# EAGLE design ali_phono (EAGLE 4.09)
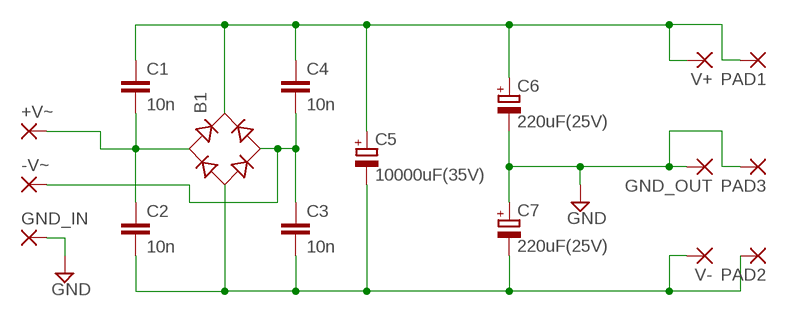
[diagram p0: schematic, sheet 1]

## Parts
+V~  3,17/1,1  [3,17/1,1]
-V~  3,17/1,1  [3,17/1,1]
B1  RB1A  [RB1A]
C1  10n  C-EU050-025X075  [C050-025X075]
C2  10n  C-EU050-025X075  [C050-025X075]
C3  10n  C-EU050-025X075  [C050-025X075]
C4  10n  C-EU050-025X075  [C050-025X075]
C5  10000uF(35V)  CPOL-EUE10-35  [EB35D]
C6  220uF(25V)  CPOL-EUE5-10.5  [E5-10,5]
C7  220uF(25V)  CPOL-EUE5-10.5  [E5-10,5]
GND_IN  3,17/1,1  [3,17/1,1]
GND_OUT  3,17/1,1  [3,17/1,1]
PAD1  3,17/1,1  [3,17/1,1]
PAD2  3,17/1,1  [3,17/1,1]
PAD3  3,17/1,1  [3,17/1,1]
V+  3,17/1,1  [3,17/1,1]
V-  3,17/1,1  [3,17/1,1]

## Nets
GND: C6.- C7.+ GND_IN.1(P) GND_OUT.1(P) PAD3.1(P)
N$1: +V~.1(P) B1.AC1 C1.2 C2.1
N$2: B1.+ C1.1 C4.1 C5.+ C6.+ PAD1.1(P) V+.1(P)
N$5: B1.- C2.2 C3.2 C5.- C7.- PAD2.1(P) V-.1(P)
N$12: -V~.1(P) B1.AC2 C3.1 C4.2

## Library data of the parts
+V~ -V~ GND_IN GND_OUT PAD1-PAD3 V+ V- = wirepad:3,17/1,1: THROUGH-HOLE PAD
B1 = rectifier:RB1A: RECTIFIER 1 A
C1-C4 = rcl:C-EU: CAPACITOR, European symbol
C5-C7 = rcl:CPOL-EU: POLARIZED CAPACITOR, European symbol

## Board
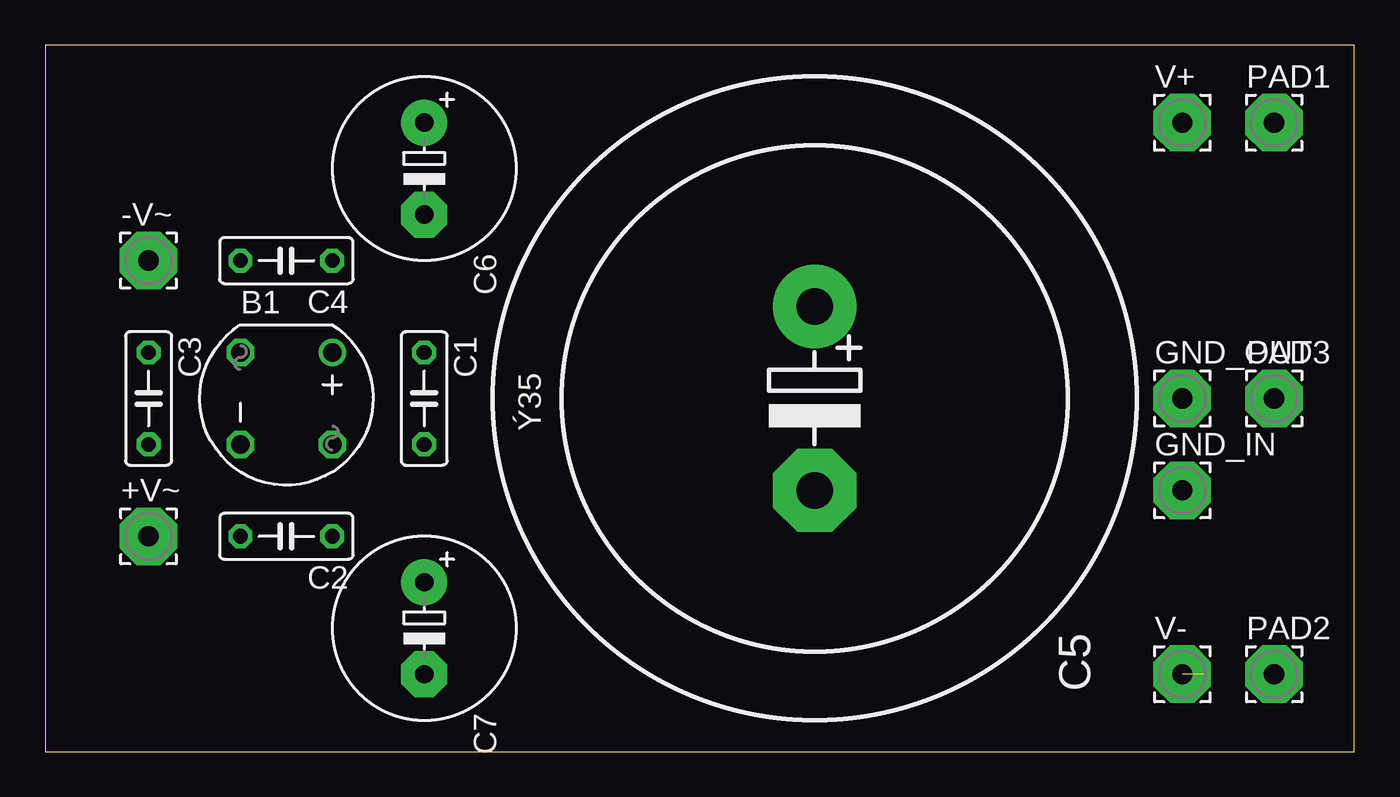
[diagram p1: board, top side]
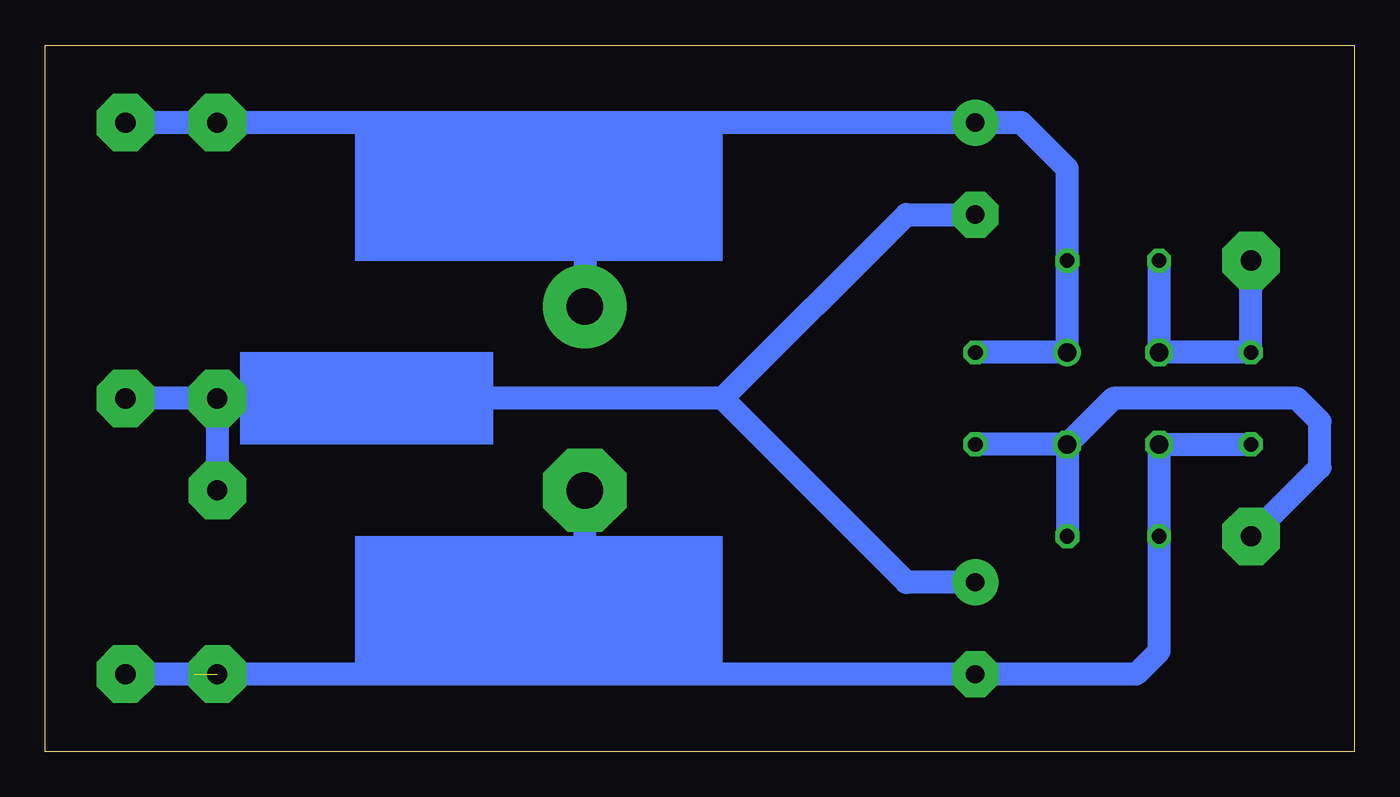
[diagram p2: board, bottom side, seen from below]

Size 72.37 x 39.04 mm. Coordinates in mm from the lower left corner, seen from the top.
Outline: 0,0 72.37,0 72.37,39.04 0,39.04 0,0
Copper layers used: Bottom

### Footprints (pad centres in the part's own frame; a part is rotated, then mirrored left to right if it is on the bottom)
3,17/1,1 = drill 1.118 pad 3.175 octagon: 1 0,0
RB1A = drill 1.016 round: + -2.54,2.54 | drill 1.016 octagon: - 2.54,-2.54; AC1 2.54,2.54; AC2 -2.54,-2.54
C050-025X075 = drill 0.813 octagon: 1 -2.54,0; 2 2.54,0
EB35D = drill 2.007 pad 4.597 round: + -5.08,0 | drill 2.007 pad 4.597 octagon: - 5.08,0
E5-10,5 = drill 1.016 pad 2.54 round: + -2.54,0 | drill 1.016 pad 2.54 octagon: - 2.54,0

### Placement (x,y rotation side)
+V~  5.71,11.9 0 top
-V~  5.71,27.14 0 top
B1  13.33,19.52 270 top
C1  20.95,19.52 270 top
C2  13.33,11.9 180 top
C3  5.71,19.52 270 top
C4  13.33,27.14 180 top
C5  42.54,19.52 270 top
C6  20.95,32.22 270 top
C7  20.95,6.82 270 top
GND_IN  62.86,14.44 0 top
GND_OUT  62.86,19.52 0 top
PAD1  67.94,34.76 0 top
PAD2  67.94,4.28 0 top
PAD3  67.94,19.52 0 top
V+  62.86,34.76 0 top
V-  62.86,4.28 0 top

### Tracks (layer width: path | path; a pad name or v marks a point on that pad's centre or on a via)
GND
  Bottom 1.27: 34.92,19.52 GND_OUT.1 | 34.92,19.52 24.76,29.68 C6.- | C7.+ 24.76,9.36 34.92,19.52 | GND_OUT.1 GND_IN.1 | GND_OUT.1 PAD3.1
N$1
  Bottom 1.27: B1.AC1 C2.1 B1.AC1 | B1.AC1 C1.2 | B1.AC1 13.33,19.52 3.17,19.52 1.9,18.25 1.9,15.71 +V~.1
N$2
  Bottom 1.27: 42.54,34.76 C6.+ 18.41,34.76 15.87,32.22 C4.1 B1.+ C1.1 | 42.54,34.76 V+.1 PAD1.1 | 42.54,34.76 C5.+
N$5  (1 unrouted)
  Bottom 1.27: 42.54,4.28 C7.- 12.06,4.28 10.79,5.55 C2.2 B1.- C3.2 | 42.54,4.28 V-.1 | 42.54,4.28 C5.- | 64.13,4.28 PAD2.1
N$12
  Bottom 1.27: C4.2 B1.AC2 C3.1 -V~.1
(copper drawn outside any net)
  shapes: Bottom area x5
